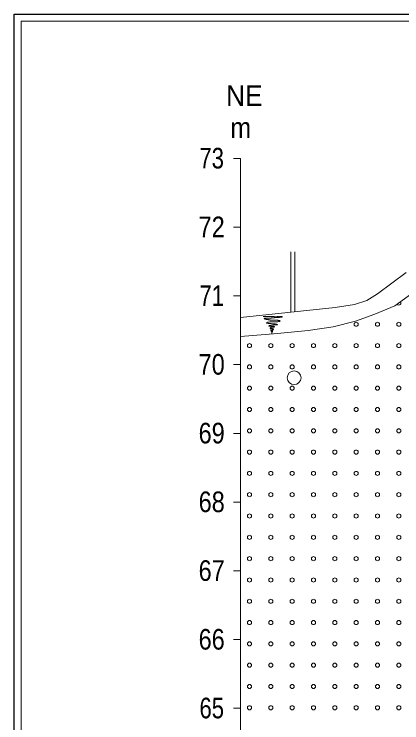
# Model space of a CAD drawing. Extents: x 640104 to 640970, y 6442278 to 6442689.
# Drawn here: x 640103.6 to 640159.9, y 6442585.9 to 6442689 of the extents above; entities that cross this region are included whole.
import ezdxf
from ezdxf.enums import TextEntityAlignment as Align

# ---------------------------------------------------------------- set-up
doc = ezdxf.new("R2010")
doc.units = 0
doc.header["$LTSCALE"] = 1.2
for name, color, linetype, lineweight in [('30', 7, 'Continuous', 13), ('31', 7, 'Continuous', 13), ('35', 7, 'Continuous', 35), ('40', 7, 'Continuous', 13), ('43', 7, 'Continuous', 13), ('47', 7, 'Continuous', 13), ('50', 7, 'Continuous', 13)]:
    doc.layers.add(name, color=color, linetype=linetype, lineweight=lineweight)

msp = doc.modelspace()

# ---------------------------------------------------------------- linework, layer by layer
at = {"layer": '30'}
msp.add_line((640136.43, 6442488), (640136.43, 6442668), dxfattribs=at)
at = {"layer": '31'}
for p, q in [((640135.43, 6442668), (640136.43, 6442668)), ((640135.43, 6442658), (640136.43, 6442658)), ((640135.43, 6442648), (640136.43, 6442648)), ((640135.43, 6442638), (640136.43, 6442638)), ((640135.43, 6442628), (640136.43, 6442628)), ((640135.43, 6442618), (640136.43, 6442618)), ((640135.43, 6442608), (640136.43, 6442608)), ((640135.43, 6442598), (640136.43, 6442598)), ((640135.43, 6442588), (640136.43, 6442588))]:
    msp.add_line(p, q, dxfattribs=at)
for points in [[(640136.43, 6442644.85), (640150.18, 6442646.29), (640153.02, 6442646.77), (640154.81, 6442647.32), (640156.37, 6442648.31), (640160.5, 6442651.42)], [(640136.43, 6442642.07), (640141.82, 6442642.54), (640146.3, 6442642.99), (640149.93, 6442643.48), (640153.17, 6442644.33), (640155.96, 6442645.33), (640158.85, 6442646.57), (640161.34, 6442648.36)]]:
    msp.add_lwpolyline(points, dxfattribs=at)
at = {"layer": '35', "lineweight": 13}
for p, q in [((640143.76, 6442654.42), (640143.76, 6442645.68)), ((640144.36, 6442654.42), (640144.36, 6442645.68))]:
    msp.add_line(p, q, dxfattribs=at)
at = {"layer": '40'}
for points in [[(640139.74, 6442644.99), (640139.78, 6442644.99), (640139.85, 6442644.99), (640139.92, 6442644.99), (640139.94, 6442644.99), (640140.01, 6442644.99), (640140.12, 6442644.99), (640140.33, 6442644.99), (640140.45, 6442644.99), (640140.48, 6442644.99), (640140.5, 6442644.99), (640140.55, 6442644.99), (640140.6, 6442644.99), (640140.68, 6442644.99), (640140.73, 6442644.99), (640140.77, 6442644.99), (640140.83, 6442644.99), (640140.88, 6442644.99), (640140.92, 6442644.99), (640140.98, 6442644.99), (640141.01, 6442644.99), (640141.06, 6442644.99), (640141.12, 6442644.99), (640141.35, 6442644.98), (640141.56, 6442644.97), (640141.62, 6442644.97), (640141.66, 6442644.97), (640141.68, 6442644.97), (640141.72, 6442644.97), (640141.76, 6442644.97), (640141.83, 6442644.98), (640141.86, 6442644.98), (640141.88, 6442644.98), (640141.9, 6442644.98), (640141.92, 6442644.98), (640141.97, 6442644.97), (640142, 6442644.97), (640142.03, 6442644.97), (640142.09, 6442644.98), (640142.13, 6442644.98), (640142.18, 6442644.99), (640142.2, 6442644.99), (640142.25, 6442644.99), (640142.28, 6442645), (640142.31, 6442645), (640142.34, 6442645), (640142.36, 6442644.99), (640142.39, 6442644.99), (640142.42, 6442644.98), (640142.44, 6442644.98)], [(640140.76, 6442644.77), (640140.74, 6442644.76), (640140.7, 6442644.76), (640140.68, 6442644.75), (640140.65, 6442644.75), (640140.63, 6442644.75), (640140.6, 6442644.75), (640140.56, 6442644.75), (640140.53, 6442644.75), (640140.48, 6442644.75), (640140.46, 6442644.75), (640140.42, 6442644.76), (640140.4, 6442644.76), (640140.37, 6442644.76), (640140.35, 6442644.76), (640140.32, 6442644.76), (640140.28, 6442644.76), (640140.24, 6442644.76), (640140.21, 6442644.76), (640140.19, 6442644.76), (640140.15, 6442644.76), (640140.12, 6442644.76), (640140.09, 6442644.76), (640140.07, 6442644.76), (640140.04, 6442644.76), (640140, 6442644.75), (640139.98, 6442644.74), (640139.95, 6442644.74), (640139.92, 6442644.73), (640139.91, 6442644.72), (640139.89, 6442644.71), (640139.88, 6442644.7), (640139.87, 6442644.67), (640139.88, 6442644.65), (640139.94, 6442644.64), (640139.98, 6442644.64), (640140, 6442644.63), (640140.04, 6442644.63), (640140.06, 6442644.62), (640140.08, 6442644.61), (640140.12, 6442644.61), (640140.15, 6442644.6), (640140.17, 6442644.59), (640140.22, 6442644.58), (640140.27, 6442644.57), (640140.32, 6442644.57), (640140.35, 6442644.56), (640140.38, 6442644.55), (640140.44, 6442644.55), (640140.51, 6442644.54)], [(640141.32, 6442644.23), (640141.26, 6442644.23), (640141.21, 6442644.23), (640141.16, 6442644.23), (640141.12, 6442644.23), (640141.08, 6442644.23), (640141.02, 6442644.23), (640140.96, 6442644.22), (640140.84, 6442644.22), (640140.79, 6442644.22), (640140.76, 6442644.21), (640140.7, 6442644.21), (640140.62, 6442644.19), (640140.53, 6442644.19), (640140.5, 6442644.19), (640140.46, 6442644.19), (640140.44, 6442644.18), (640140.42, 6442644.17), (640140.4, 6442644.17), (640140.37, 6442644.16), (640140.35, 6442644.15), (640140.33, 6442644.14), (640140.29, 6442644.11), (640140.27, 6442644.1), (640140.26, 6442644.08), (640140.24, 6442644.07), (640140.23, 6442644.06), (640140.21, 6442644.04), (640140.2, 6442644.03), (640140.22, 6442644.02), (640140.24, 6442644.02), (640140.28, 6442644.02), (640140.32, 6442644.02), (640140.39, 6442644.01), (640140.44, 6442644), (640140.51, 6442643.99), (640140.59, 6442643.99), (640140.63, 6442643.99), (640140.67, 6442643.97), (640140.71, 6442643.97), (640140.82, 6442643.97), (640140.91, 6442643.97), (640140.98, 6442643.96), (640141.05, 6442643.95), (640141.15, 6442643.95), (640141.24, 6442643.95), (640141.32, 6442643.92), (640141.38, 6442643.92), (640141.44, 6442643.92), (640141.5, 6442643.91)], [(640140.51, 6442644.54), (640140.6, 6442644.52), (640140.67, 6442644.51), (640140.71, 6442644.5), (640140.77, 6442644.49), (640140.84, 6442644.49), (640140.88, 6442644.48), (640140.92, 6442644.48), (640140.96, 6442644.47), (640141.01, 6442644.47), (640141.05, 6442644.47), (640141.11, 6442644.46), (640141.16, 6442644.46), (640141.21, 6442644.46), (640141.28, 6442644.46), (640141.33, 6442644.45), (640141.37, 6442644.45), (640141.4, 6442644.45), (640141.44, 6442644.45), (640141.49, 6442644.45), (640141.55, 6442644.45), (640141.61, 6442644.45), (640141.67, 6442644.45), (640141.71, 6442644.45), (640141.76, 6442644.45), (640141.79, 6442644.45), (640141.83, 6442644.45), (640141.87, 6442644.45), (640141.91, 6442644.44), (640141.95, 6442644.44), (640141.98, 6442644.43), (640142.07, 6442644.43), (640142.11, 6442644.41), (640142.15, 6442644.39), (640142.18, 6442644.39), (640142.2, 6442644.38), (640142.2, 6442644.35), (640142.2, 6442644.33), (640142.18, 6442644.32), (640142.16, 6442644.31), (640142.15, 6442644.3), (640142.12, 6442644.29), (640142.06, 6442644.27), (640141.96, 6442644.27), (640141.88, 6442644.25), (640141.83, 6442644.24), (640141.76, 6442644.24), (640141.71, 6442644.23), (640141.64, 6442644.23), (640141.56, 6442644.23), (640141.43, 6442644.23), (640141.32, 6442644.23)], [(640142.44, 6442644.98), (640142.48, 6442644.97), (640142.5, 6442644.97), (640142.53, 6442644.97), (640142.55, 6442644.95), (640142.53, 6442644.95), (640142.54, 6442644.95), (640142.52, 6442644.95), (640142.48, 6442644.94), (640142.44, 6442644.93), (640142.42, 6442644.93), (640142.39, 6442644.93), (640142.36, 6442644.92), (640142.34, 6442644.92), (640142.32, 6442644.91), (640142.28, 6442644.91), (640142.24, 6442644.9), (640142.21, 6442644.9), (640142.13, 6442644.89), (640142.1, 6442644.88), (640142.08, 6442644.88), (640142.04, 6442644.87), (640142.01, 6442644.87), (640141.99, 6442644.87), (640141.95, 6442644.87), (640141.92, 6442644.87), (640141.85, 6442644.87), (640141.81, 6442644.87), (640141.76, 6442644.87), (640141.71, 6442644.87), (640141.67, 6442644.86), (640141.64, 6442644.86), (640141.6, 6442644.85), (640141.56, 6442644.85), (640141.44, 6442644.85), (640141.42, 6442644.85), (640141.4, 6442644.84), (640141.35, 6442644.83), (640141.28, 6442644.83), (640141.23, 6442644.82), (640141.19, 6442644.82), (640141.13, 6442644.81), (640141.09, 6442644.81), (640141.06, 6442644.79), (640141.02, 6442644.79), (640141, 6442644.79), (640140.98, 6442644.79), (640140.94, 6442644.79), (640140.91, 6442644.78), (640140.88, 6442644.78), (640140.8, 6442644.77), (640140.76, 6442644.77)], [(640141.5, 6442643.91), (640141.53, 6442643.91), (640141.56, 6442643.91), (640141.62, 6442643.89), (640141.67, 6442643.88), (640141.7, 6442643.87), (640141.73, 6442643.86), (640141.77, 6442643.85), (640141.79, 6442643.84), (640141.8, 6442643.81), (640141.78, 6442643.8), (640141.76, 6442643.79), (640141.74, 6442643.79), (640141.66, 6442643.78), (640141.62, 6442643.78), (640141.6, 6442643.78), (640141.55, 6442643.78), (640141.49, 6442643.78), (640141.44, 6442643.77), (640141.4, 6442643.77), (640141.37, 6442643.77), (640141.28, 6442643.77), (640141.24, 6442643.75), (640141.21, 6442643.75), (640141.17, 6442643.75), (640141.15, 6442643.75), (640141.11, 6442643.75), (640141.05, 6442643.75), (640141, 6442643.74), (640140.95, 6442643.73), (640140.91, 6442643.72), (640140.88, 6442643.72), (640140.85, 6442643.72), (640140.83, 6442643.71), (640140.79, 6442643.71), (640140.78, 6442643.7), (640140.74, 6442643.69), (640140.72, 6442643.68), (640140.7, 6442643.68), (640140.67, 6442643.67), (640140.63, 6442643.67), (640140.59, 6442643.66), (640140.56, 6442643.64), (640140.54, 6442643.63), (640140.54, 6442643.59), (640140.56, 6442643.59), (640140.61, 6442643.59), (640140.68, 6442643.59), (640140.73, 6442643.59), (640140.76, 6442643.59), (640140.83, 6442643.58), (640140.87, 6442643.58)], [(640140.87, 6442643.58), (640140.88, 6442643.57), (640140.91, 6442643.57), (640140.95, 6442643.57), (640141, 6442643.57), (640141.02, 6442643.57), (640141.09, 6442643.56), (640141.15, 6442643.56), (640141.17, 6442643.56), (640141.2, 6442643.56), (640141.23, 6442643.56), (640141.27, 6442643.56), (640141.31, 6442643.55), (640141.34, 6442643.54), (640141.37, 6442643.53), (640141.4, 6442643.52), (640141.43, 6442643.51), (640141.43, 6442643.48), (640141.35, 6442643.47), (640141.24, 6442643.46), (640141.2, 6442643.46), (640141.13, 6442643.45), (640141.09, 6442643.45), (640141.04, 6442643.45), (640141, 6442643.44), (640140.95, 6442643.44), (640140.9, 6442643.43), (640140.84, 6442643.4), (640140.83, 6442643.39), (640140.8, 6442643.37), (640140.78, 6442643.35), (640140.76, 6442643.34), (640140.76, 6442643.31), (640140.74, 6442643.29), (640140.76, 6442643.28), (640140.79, 6442643.27), (640140.84, 6442643.26), (640140.92, 6442643.26), (640141, 6442643.25), (640141.04, 6442643.24), (640141.07, 6442643.23), (640141.12, 6442643.23), (640141.17, 6442643.23), (640141.24, 6442643.2), (640141.24, 6442643.17), (640141.23, 6442643.15), (640141.22, 6442643.13), (640141.17, 6442643.09), (640141.15, 6442643.08), (640141.11, 6442643.08), (640141.05, 6442643.08), (640141, 6442643.08), (640140.95, 6442643.08), (640140.89, 6442643.08), (640140.84, 6442643.07), (640140.83, 6442643.04), (640140.82, 6442643.03), (640140.83, 6442643.01), (640140.85, 6442643), (640140.93, 6442642.98), (640140.99, 6442642.97), (640141.02, 6442642.96), (640141.06, 6442642.95), (640141.1, 6442642.95), (640141.12, 6442642.93), (640141.11, 6442642.92), (640141.07, 6442642.92), (640141.02, 6442642.91), (640140.96, 6442642.91), (640140.93, 6442642.91), (640140.91, 6442642.9), (640140.91, 6442642.87), (640140.92, 6442642.85), (640140.94, 6442642.84), (640140.96, 6442642.83), (640141, 6442642.82), (640141.04, 6442642.81), (640141.07, 6442642.8), (640141.08, 6442642.77), (640141.06, 6442642.75), (640141.05, 6442642.73), (640141.04, 6442642.71), (640141.02, 6442642.69), (640141.02, 6442642.66), (640141.02, 6442642.63), (640141.02, 6442642.6), (640141.01, 6442642.58), (640141.01, 6442642.55), (640141, 6442642.53), (640141, 6442642.5), (640140.99, 6442642.47), (640140.99, 6442642.44), (640140.99, 6442642.43), (640140.99, 6442642.46)]]:
    msp.add_lwpolyline(points, dxfattribs=at)
at = {"layer": '43'}
for centre in [(640153.249, 6442643.873), (640156.349, 6442643.873), (640159.449, 6442643.873), (640137.749, 6442640.773), (640140.849, 6442640.773), (640143.949, 6442640.773), (640147.049, 6442640.773), (640150.149, 6442640.773), (640153.249, 6442640.773), (640156.349, 6442640.773), (640159.449, 6442640.773), (640137.749, 6442637.673), (640140.849, 6442637.673), (640143.949, 6442637.673), (640147.049, 6442637.673), (640150.149, 6442637.673), (640153.249, 6442637.673), (640156.349, 6442637.673), (640159.449, 6442637.673), (640137.749, 6442634.573), (640140.849, 6442634.573), (640143.949, 6442634.573), (640147.049, 6442634.573), (640150.149, 6442634.573), (640153.249, 6442634.573), (640156.349, 6442634.573), (640159.449, 6442634.573), (640137.749, 6442631.473), (640140.849, 6442631.473), (640143.949, 6442631.473), (640147.049, 6442631.473), (640150.149, 6442631.473), (640153.249, 6442631.473), (640156.349, 6442631.473), (640159.449, 6442631.473), (640137.749, 6442628.373), (640140.849, 6442628.373), (640143.949, 6442628.373), (640147.049, 6442628.373), (640150.149, 6442628.373), (640153.249, 6442628.373), (640156.349, 6442628.373), (640159.449, 6442628.373), (640137.749, 6442625.273), (640140.849, 6442625.273), (640143.949, 6442625.273), (640147.049, 6442625.273), (640150.149, 6442625.273), (640153.249, 6442625.273), (640156.349, 6442625.273), (640159.449, 6442625.273), (640137.749, 6442622.173), (640140.849, 6442622.173), (640143.949, 6442622.173), (640147.049, 6442622.173), (640150.149, 6442622.173), (640153.249, 6442622.173), (640156.349, 6442622.173), (640159.449, 6442622.173), (640137.749, 6442619.073), (640140.849, 6442619.073), (640143.949, 6442619.073), (640147.049, 6442619.073), (640150.149, 6442619.073), (640153.249, 6442619.073), (640156.349, 6442619.073), (640159.449, 6442619.073), (640137.749, 6442615.973), (640140.849, 6442615.973), (640143.949, 6442615.973), (640147.049, 6442615.973), (640150.149, 6442615.973), (640153.249, 6442615.973), (640156.349, 6442615.973), (640159.449, 6442615.973), (640137.749, 6442612.873), (640140.849, 6442612.873), (640143.949, 6442612.873), (640147.049, 6442612.873), (640150.149, 6442612.873), (640153.249, 6442612.873), (640156.349, 6442612.873), (640159.449, 6442612.873), (640137.749, 6442609.773), (640140.849, 6442609.773), (640143.949, 6442609.773), (640147.049, 6442609.773), (640150.149, 6442609.773), (640153.249, 6442609.773), (640156.349, 6442609.773), (640159.449, 6442609.773), (640137.749, 6442606.673), (640140.849, 6442606.673), (640143.949, 6442606.673), (640147.049, 6442606.673), (640150.149, 6442606.673), (640153.249, 6442606.673), (640156.349, 6442606.673), (640159.449, 6442606.673), (640137.749, 6442603.573), (640140.849, 6442603.573), (640143.949, 6442603.573), (640147.049, 6442603.573), (640150.149, 6442603.573), (640153.249, 6442603.573), (640156.349, 6442603.573), (640159.449, 6442603.573), (640137.749, 6442600.473), (640140.849, 6442600.473), (640143.949, 6442600.473), (640147.049, 6442600.473), (640150.149, 6442600.473), (640153.249, 6442600.473), (640156.349, 6442600.473), (640159.449, 6442600.473), (640137.749, 6442597.373), (640140.849, 6442597.373), (640143.949, 6442597.373), (640147.049, 6442597.373), (640150.149, 6442597.373), (640153.249, 6442597.373), (640156.349, 6442597.373), (640159.449, 6442597.373), (640137.749, 6442594.273), (640140.849, 6442594.273), (640143.949, 6442594.273), (640147.049, 6442594.273), (640150.149, 6442594.273), (640153.249, 6442594.273), (640156.349, 6442594.273), (640159.449, 6442594.273), (640137.749, 6442591.173), (640140.849, 6442591.173), (640143.949, 6442591.173), (640147.049, 6442591.173), (640150.149, 6442591.173), (640153.249, 6442591.173), (640156.349, 6442591.173), (640159.449, 6442591.173), (640137.749, 6442588.073), (640140.849, 6442588.073), (640143.949, 6442588.073), (640147.049, 6442588.073), (640150.149, 6442588.073), (640153.249, 6442588.073), (640156.349, 6442588.073), (640159.449, 6442588.073)]:
    msp.add_circle(centre, 0.3, dxfattribs=at)
msp.add_arc((640159.449, 6442646.973), 0.3, 210.72929, 40.77848, dxfattribs=at)
at = {"layer": '47'}
msp.add_circle((640144.236, 6442636.089), 1, dxfattribs=at)
at = {"layer": '50', "lineweight": 25}
msp.add_lwpolyline([(640103.56, 6442688.99), (640970.3, 6442688.99), (640970.3, 6442282.54), (640103.56, 6442282.54)], close=True, dxfattribs=at)
at = {"layer": '50'}
msp.add_lwpolyline([(640104.56, 6442687.99), (640969.3, 6442687.99), (640969.3, 6442283.54), (640104.56, 6442283.54)], close=True, dxfattribs=at)

# ---------------------------------------------------------------- texts
at = {"layer": '30'}
for s, width, p in [('NE', 0.95, (640136.995, 6442675.65)), ('m', 0.9, (640136.48, 6442670.97)), ('73', 0.8, (640132.255, 6442666.54)), ('72', 0.85, (640132.255, 6442656.54)), ('71', 0.8, (640132.26, 6442646.54)), ('70', 0.85, (640132.255, 6442636.54)), ('69', 0.85, (640132.255, 6442626.54)), ('68', 0.85, (640132.26, 6442616.54)), ('67', 0.85, (640132.255, 6442606.54)), ('66', 0.85, (640132.255, 6442596.54)), ('65', 0.8, (640132.265, 6442586.54))]:
    msp.add_text(s, height=3, dxfattribs=dict(at, width=width)).set_placement(p, align=Align.CENTER)

doc.saveas('drawing.dxf')
